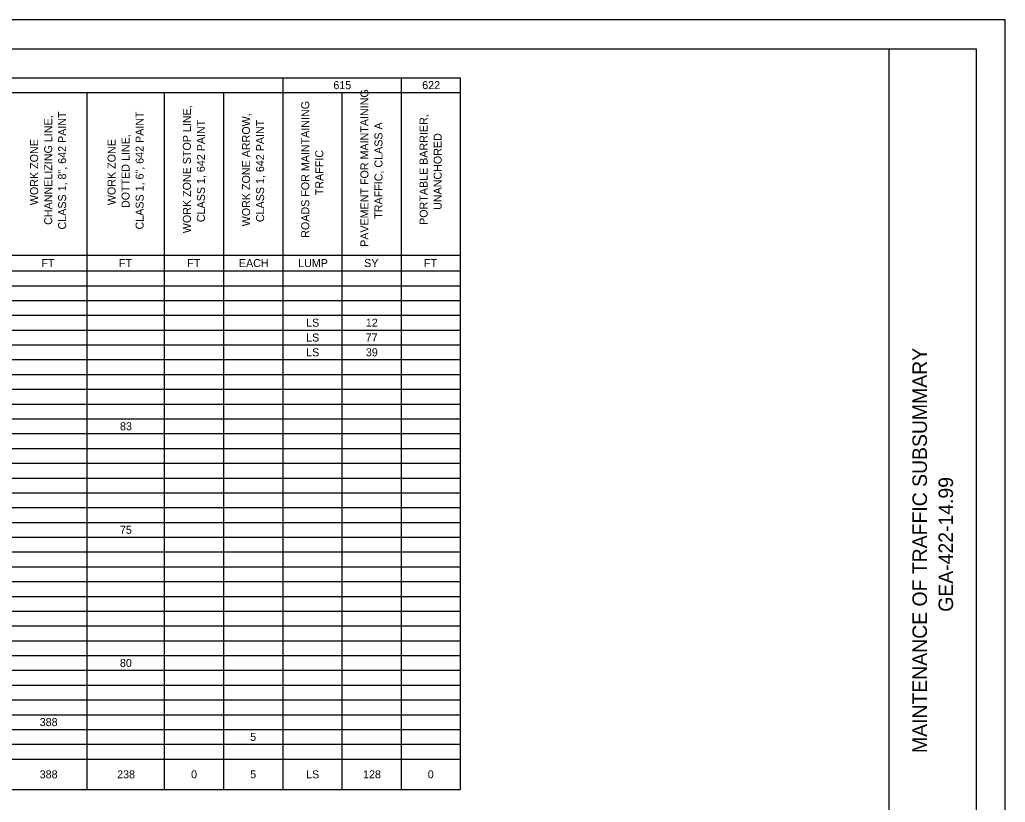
# Model space of a CAD drawing. Extents: x 0 to 34, y 0 to 22.
# Drawn here: x 17.01 to 34, y 8.51 to 22 of the extents above; entities that cross this region are included whole.
import ezdxf

# ---------------------------------------------------------------- set-up
doc = ezdxf.new("R2010")
doc.units = 0
for name, color, linetype in [('SH_Border', 7, 'Continuous'), ('SH_Cut_Line', 7, 'Continuous'), ('SH_Data', 7, 'Continuous'), ('SH_Text', 7, 'Continuous')]:
    doc.layers.add(name, color=color, linetype=linetype)

msp = doc.modelspace()

# ---------------------------------------------------------------- linework, layer by layer
at = {"layer": 'SH_Border'}
msp.add_line((32, 0.5), (32, 21.5), dxfattribs=at)
msp.add_lwpolyline([(1.5, 21.5), (33.5, 21.5), (33.5, 0.5), (1.5, 0.5)], close=True, dxfattribs=at)
at = {"layer": 'SH_Cut_Line'}
msp.add_lwpolyline([(0, 0), (34, 0), (34, 22), (0, 22)], close=True, dxfattribs=at)
at = {"layer": 'SH_Text'}
for p, q in [((2, 21), (24.605, 21)), ((21.545, 21), (21.545, 8.73)), ((23.585, 21), (23.585, 8.73)), ((24.605, 21), (24.605, 8.73)), ((8.045, 20.745), (24.605, 20.745)), ((18.17, 20.745), (18.17, 8.73)), ((19.505, 20.745), (19.505, 8.73)), ((20.525, 20.745), (20.525, 8.73)), ((22.565, 20.745), (22.565, 8.73)), ((8.045, 17.94), (24.605, 17.94)), ((2, 17.67), (24.605, 17.67)), ((2, 17.415), (24.605, 17.415)), ((2, 17.16), (24.605, 17.16)), ((2, 16.905), (24.605, 16.905)), ((2, 16.65), (24.605, 16.65)), ((2, 16.395), (24.605, 16.395)), ((2, 16.14), (24.605, 16.14)), ((2, 15.885), (24.605, 15.885)), ((2, 15.63), (24.605, 15.63)), ((2, 15.375), (24.605, 15.375)), ((2, 15.12), (24.605, 15.12)), ((2, 14.865), (24.605, 14.865)), ((2, 14.61), (24.605, 14.61)), ((2, 14.355), (24.605, 14.355)), ((2, 14.1), (24.605, 14.1)), ((2, 13.845), (24.605, 13.845)), ((2, 13.59), (24.605, 13.59)), ((2, 13.335), (24.605, 13.335)), ((2, 13.08), (24.605, 13.08)), ((2, 12.825), (24.605, 12.825)), ((2, 12.57), (24.605, 12.57)), ((2, 12.315), (24.605, 12.315)), ((2, 12.06), (24.605, 12.06)), ((2, 11.805), (24.605, 11.805)), ((2, 11.55), (24.605, 11.55)), ((2, 11.295), (24.605, 11.295)), ((2, 11.04), (24.605, 11.04)), ((2, 10.785), (24.605, 10.785)), ((2, 10.53), (24.605, 10.53)), ((2, 10.275), (24.605, 10.275)), ((2, 10.02), (24.605, 10.02)), ((2, 9.765), (24.605, 9.765)), ((2, 9.51), (24.605, 9.51)), ((2, 9.255), (24.605, 9.255)), ((2, 8.73), (24.605, 8.73))]:
    msp.add_line(p, q, dxfattribs=at)

# ---------------------------------------------------------------- texts
at = {"layer": 'SH_Data'}
for s, p in [('MAINTENANCE OF TRAFFIC SUBSUMMARY', (32.65, 9.359)), ('GEA-422-14.99', (33.1, 11.794))]:
    msp.add_text(s, height=0.25, rotation=90, dxfattribs=at).set_placement(p)
at = {"layer": 'SH_Text'}
for s, p in [('615', (22.419, 20.803)), ('622', (23.95, 20.803)), ('FT', (17.388, 17.736)), ('FT', (18.723, 17.736)), ('FT', (19.9, 17.736)), ('EACH', (20.791, 17.736)), ('LUMP', (21.811, 17.736)), ('SY', (22.95, 17.736)), ('FT', (23.98, 17.736)), ('LS', (21.949, 16.709)), ('12', (22.978, 16.709)), ('LS', (21.949, 16.453)), ('77', (22.975, 16.453)), ('LS', (21.949, 16.198)), ('39', (22.979, 16.198)), ('83', (18.741, 14.923)), ('75', (18.74, 13.138)), ('80', (18.74, 10.843)), ('388', (17.357, 9.823)), ('5', (20.985, 9.569)), ('388', (17.357, 8.923)), ('238', (18.692, 8.923)), ('0', (19.966, 8.923)), ('5', (20.985, 8.923)), ('LS', (21.949, 8.923)), ('128', (22.93, 8.923)), ('0', (24.046, 8.923))]:
    msp.add_text(s, height=0.138, dxfattribs=at).set_placement(p)
for s, p in [('PAVEMENT FOR MAINTAINING ', (23.023, 18.084)), ('ROADS FOR MAINTAINING ', (22.003, 18.241)), ('CLASS 1, 8", 642 PAINT', (17.813, 18.384)), ('CLASS 1, 6", 642 PAINT', (19.148, 18.384)), ('WORK ZONE STOP LINE, ', (19.963, 18.32)), ('CHANNELIZING LINE,', (17.572, 18.464)), ('CLASS 1, 642 PAINT', (20.205, 18.511)), ('WORK ZONE ARROW, ', (20.983, 18.439)), ('CLASS 1, 642 PAINT', (21.225, 18.511)), ('TRAFFIC, CLASS A', (23.265, 18.569)), ('PORTABLE BARRIER, ', (24.043, 18.463)), ('WORK ZONE', (17.33, 18.803)), ('WORK ZONE', (18.665, 18.803)), ('DOTTED LINE,', (18.906, 18.754)), ('UNANCHORED', (24.285, 18.721)), ('TRAFFIC', (22.245, 18.975))]:
    msp.add_text(s, height=0.138, rotation=90, dxfattribs=at).set_placement(p)

doc.saveas('drawing.dxf')
